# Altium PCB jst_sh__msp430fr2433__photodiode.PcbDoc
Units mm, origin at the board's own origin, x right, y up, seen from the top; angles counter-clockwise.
Board outline 56 x 30 mm, 2 copper layers (Top, Bottom), stack 0 mm thick; 17 components, 9 nets, 70 pads, 27 vias.
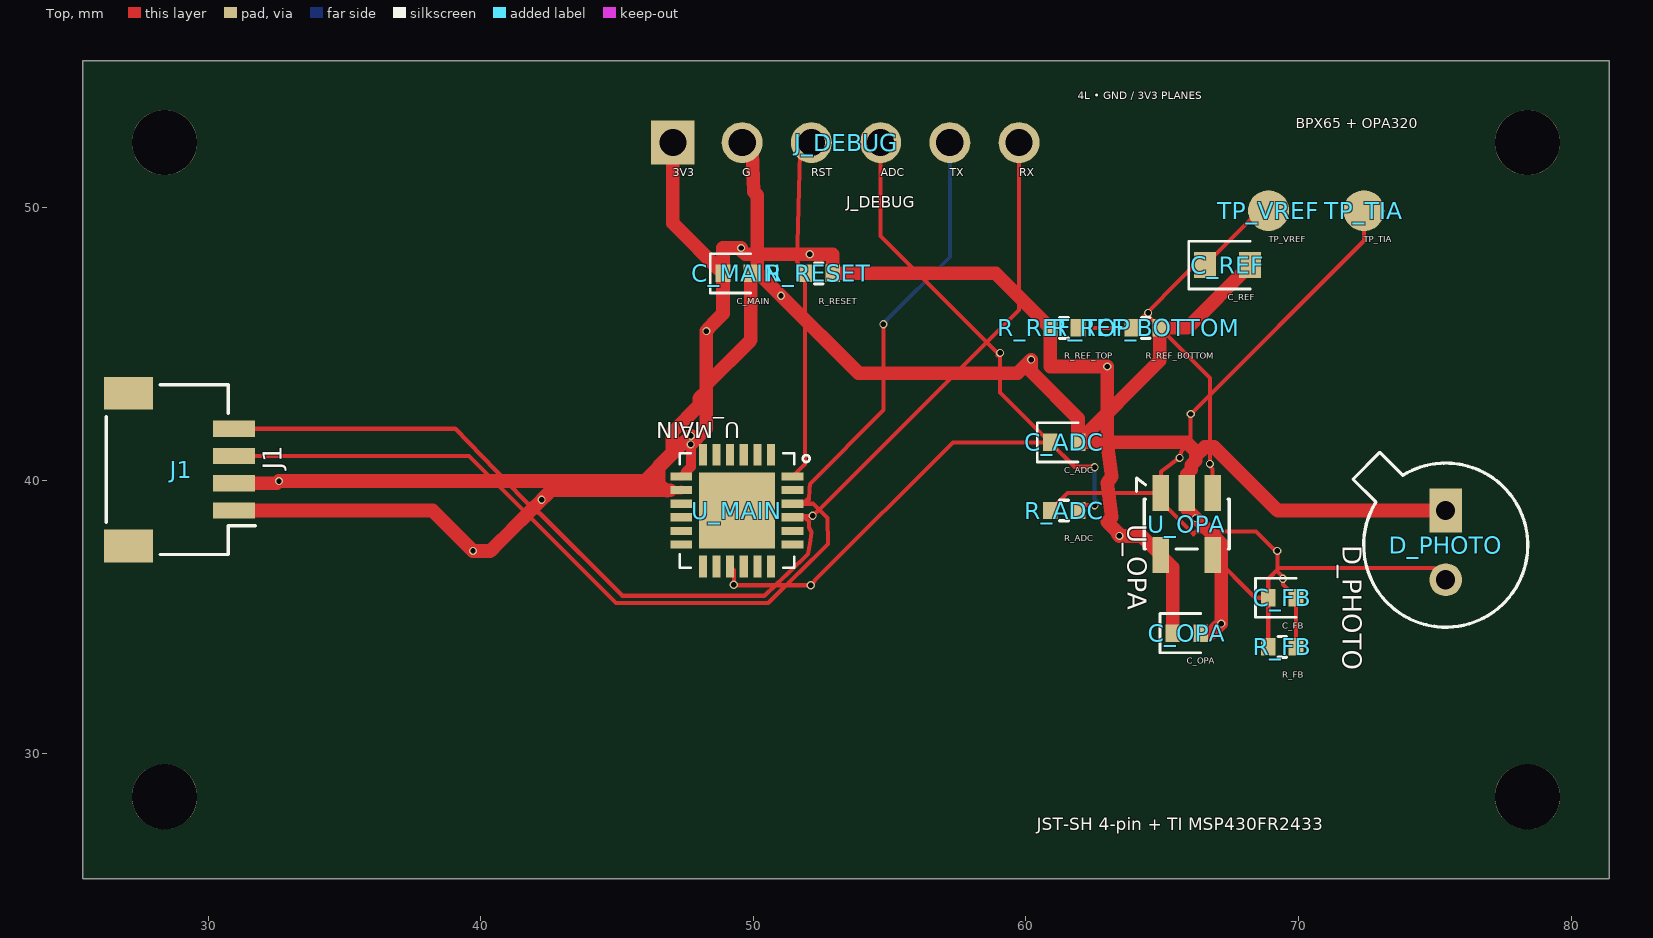
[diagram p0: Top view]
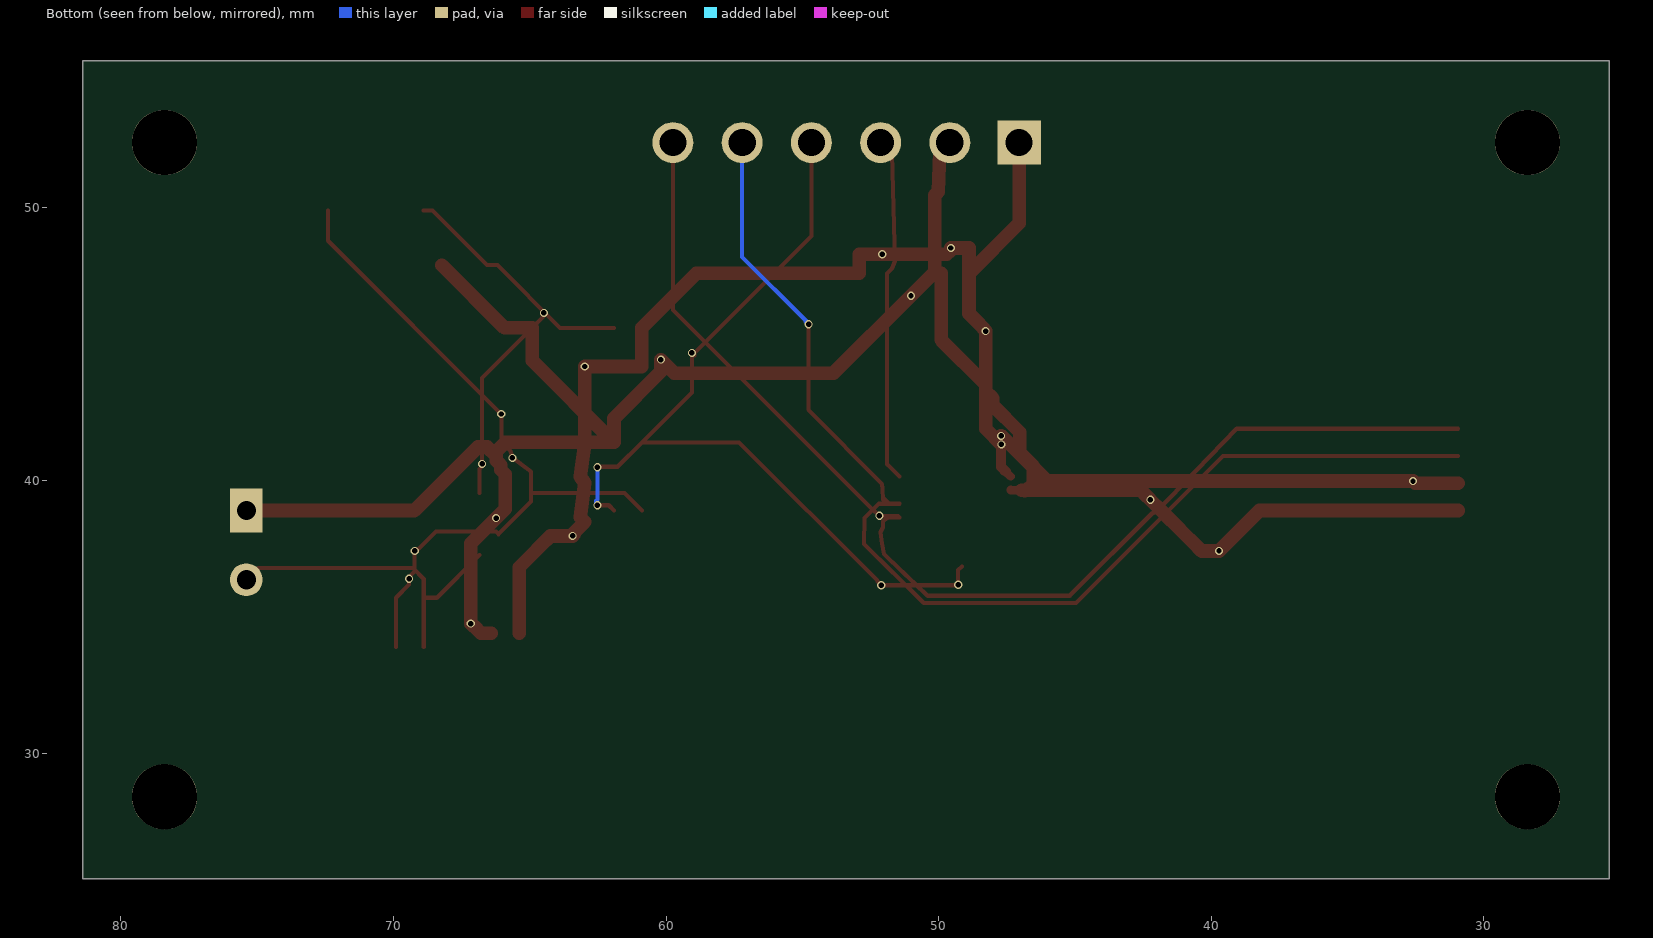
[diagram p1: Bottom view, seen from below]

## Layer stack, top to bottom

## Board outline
25.4,55.4 81.4,55.4 81.4,25.4 25.4,25.4

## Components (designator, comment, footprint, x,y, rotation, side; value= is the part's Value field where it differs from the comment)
C_ADC "" TSCIRCUIT-1.5600x0.6400mm 61.4,41.4 r0 top
C_FB "" TSCIRCUIT-1.5600x0.6400mm 69.4,35.7 r0 top
C_MAIN "" TSCIRCUIT-1.5600x0.6400mm 49.4,47.6 r0 top
C_OPA "" TSCIRCUIT-1.5600x0.6400mm 65.9,34.4 r0 top
C_REF "" TSCIRCUIT-2.4500x0.9500mm 67.4,47.9 r0 top
D_PHOTO "" TSCIRCUIT-1.2000x3.9400mm 75.4,37.73 r270 top
J1 "" TSCIRCUIT-5.5500x6.8000mm 28.95,40.4 r90 top
J_DEBUG "" TSCIRCUIT-14.2000x1.5000mm 53.4,52.4 r0 top
R_ADC "" TSCIRCUIT-1.5600x0.6400mm 61.4,38.9 r0 top
R_FB "" TSCIRCUIT-1.5600x0.6400mm 69.4,33.9 r0 top
R_REF_BOTTOM "" TSCIRCUIT-1.5600x0.6400mm 64.4,45.6 r0 top
R_REF_TOP "" TSCIRCUIT-1.5600x0.6400mm 61.4,45.6 r0 top
R_RESET "" TSCIRCUIT-1.5600x0.6400mm 52.4,47.6 r0 top
TP_TIA "" TSCIRCUIT-1.5000x1.5000mm 72.4,49.9 r0 top
TP_VREF "" TSCIRCUIT-1.5000x1.5000mm 68.9,49.9 r0 top
U_MAIN "" TSCIRCUIT-4.8833x4.8963mm 49.4,38.9 r180 top
U_OPA "" TSCIRCUIT-2.5000x3.6000mm 65.9,38.4 r270 top

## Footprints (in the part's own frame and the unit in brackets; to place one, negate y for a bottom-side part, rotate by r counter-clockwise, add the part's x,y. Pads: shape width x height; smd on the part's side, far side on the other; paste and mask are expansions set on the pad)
TSCIRCUIT-1.2000x3.9400mm [mm]
  rect 1.6x1.2 hole 0.7: 1(-1.17,0)
  round 1.2 hole 0.7: 2(1.37,0)
  silkscreen extent -3.3,-3.4 3.11,3.01
TSCIRCUIT-1.5000x1.5000mm [mm]
  round 1.5 smd: 1(0,0)
TSCIRCUIT-1.5600x0.6400mm [mm]
  rect 0.54x0.64 smd: 1(-0.51,0) 2(0.51,0)
  silkscreen extent -0.98,-0.72 0.51,0.72
TSCIRCUIT-2.4500x0.9500mm [mm]
  rect 0.8x0.95 smd: 1(-0.825,0) 2(0.825,0)
  silkscreen extent -1.43,-0.87 0.82,0.87
TSCIRCUIT-2.5000x3.6000mm [mm]
  rect 1.325x0.6 smd: 1(-1.138,-0.95) 2(-1.138,0) 3(-1.138,0.95) 4(1.137,0.95) 5(1.137,-0.95)
  silkscreen extent -1.69,-1.84 0.91,1.56
TSCIRCUIT-4.8833x4.8963mm [mm]
  rect 0.8x0.3 smd: 1(-2.042,-1.25) 2(-2.042,-0.75) 3(-2.042,-0.25) 4(-2.042,0.25) 5(-2.042,0.75) 6(-2.042,1.25) 13(2.042,1.25) 14(2.042,0.75) 15(2.042,0.25) 16(2.042,-0.25) 17(2.042,-0.75) 18(2.042,-1.25)
  rect 0.3x0.8 smd: 7(-1.25,2.048) 8(-0.75,2.048) 9(-0.25,2.048) 10(0.25,2.048) 11(0.75,2.048) 12(1.25,2.048) 19(1.25,-2.048) 20(0.75,-2.048) 21(0.25,-2.048) 22(-0.25,-2.048) 23(-0.75,-2.048) 24(-1.25,-2.048)
  rect 2.8x2.8 smd: 25(-0.001,0.001)
  silkscreen extent -2.67,-2.1 2.1,2.1
TSCIRCUIT-5.5500x6.8000mm [mm]
  rect 1.2x1.8 smd: 1(-2.8,1.875) 1(2.8,1.875)
  rect 0.6x1.55 smd: 1(-1.5,-2) 2(-0.5,-2) 3(0.5,-2) 4(1.5,-2)
  silkscreen extent -3.11,-2.77 3.11,2.69
TSCIRCUIT-14.2000x1.5000mm [mm]
  rect 1.6x1.6 hole 1: 1(-6.35,0)
  round 1.5 hole 1: 2(-3.81,0) 3(-1.27,0) 4(1.27,0) 5(3.81,0) 6(6.35,0)

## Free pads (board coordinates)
  round 2.4 hole 2.4 unplated: NPTH-1(28.4,28.4) NPTH-2(78.4,52.4) NPTH-3(78.4,28.4) NPTH-4(28.4,52.4)

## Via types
v1: diameter 0.3, hole 0.2, Top to Bottom, 27 vias

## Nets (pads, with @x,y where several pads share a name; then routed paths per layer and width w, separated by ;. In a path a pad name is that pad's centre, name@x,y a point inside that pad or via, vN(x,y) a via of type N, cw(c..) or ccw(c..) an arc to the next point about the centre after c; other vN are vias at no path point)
ADC_IN: C_ADC.1 J_DEBUG.4 R_ADC.2 U_MAIN.10 | length 32.4
  Top w0.15: U_MAIN.10 49.284,36.718 v1(49.284,36.18) 49.305,36.159 49.36,36.159 v1(52.11,36.159) 52.242,36.291 52.242,36.324 57.318,41.4 C_ADC.1 ; J_DEBUG.4 54.67,48.969 58.962,44.678 58.962,44.581 v1(59.054,44.684) 59.054,43.236 C_ADC.1 ; R_ADC.2 62.103,39.093 v1(62.522,39.093) ; v1(62.521,40.49) 62.505,40.506 61.784,40.506 C_ADC.1
  Bottom w0.15: v1(62.521,40.49) 62.521,39.299 62.561,39.258 62.561,39.132 v1(62.522,39.093)
GND: C_ADC.2 C_MAIN.2 C_OPA.2 C_REF.2 D_PHOTO.1 J1.1@30.95,38.9 J_DEBUG.2 R_REF_BOTTOM.2 U_MAIN.17 U_OPA.2 | length 82.7
  Top w0.3: U_MAIN.17@46.958,39.65 46.983,39.65 47.077,39.65 47.171,39.65 47.264,39.65 U_MAIN.17
  Top w0.324: U_MAIN.17@46.958,39.638 47.098,39.642 U_MAIN.17
  Top w0.475: 46.795,39.65 46.889,39.65 46.958,39.65 ; 46.838,39.634 U_MAIN.17@46.958,39.638
  Top w0.5: J1.1@30.95,38.9 38.233,38.9 v1(39.716,37.417) 40.036,37.417 40.356,37.417 40.663,37.724 40.971,38.032 41.278,38.339 41.585,38.646 41.893,38.954 42.2,39.261 v1(42.234,39.295) 42.412,39.472 42.589,39.65 43.036,39.65 43.482,39.65 43.929,39.65 44.375,39.65 44.822,39.65 45.268,39.65 45.715,39.65 46.161,39.65 46.608,39.65 46.702,39.65 46.795,39.65 ; 46.838,39.634 46.6,39.8 46.525,39.875 46.525,40.525 47.025,41.025 47.025,41.775 48.025,42.775 48.025,43.025 48.275,43.275 48.275,43.525 49.91,45.16 49.91,45.308 49.91,45.766 49.91,46.225 49.91,46.683 49.91,47.142 C_MAIN.2 ; J_DEBUG.2 49.774,52.223 49.951,52.047 49.958,52.047 49.979,51.561 50,51.076 50.021,50.59 50.15,50.461 50.15,48.65 50.146,47.677 C_MAIN.2 ; C_OPA.2 66.788,34.4 67.051,34.663 67.078,34.663 v1(67.165,34.75) 67.165,37.69 v1(66.234,38.621) 65.9,38.955 U_OPA.2 ; C_REF.2 65.925,45.6 R_REF_BOTTOM.2 64.91,44.4 C_ADC.2 ; D_PHOTO.1 69.233,38.9 66.9,41.233 66.567,41.233 66.233,40.9 66.233,40.733 ; C_MAIN.2 50.197,47.6 v1(51.016,46.781) 53.856,43.941 59.64,43.941 59.697,43.941 v1(60.192,44.436) 60.192,43.997 61.91,42.279 C_ADC.2 ; C_ADC.2 62.067,41.4 65.9,41.4 66.233,41.067 66.233,40.733 ; U_OPA.2 65.9,40.233 ; U_OPA.2 65.9,40.233 ; 65.9,40.233 66.067,40.4 ; 65.9,40.233 66.067,40.4 ; 66.067,40.4 66.067,40.567 ; 66.067,40.4 66.067,40.567 ; 66.067,40.567 66.233,40.733 ; 66.067,40.567 66.233,40.733
MAIN_RESET: J_DEBUG.3 R_RESET.1 U_MAIN.1 | length 12.7
  Top w0.15: U_MAIN.1 51.89,40.598 R_RESET.1 51.713,47.777 51.6,48.05 51.713,51.983 J_DEBUG.3
PD_SUM: C_FB.1 D_PHOTO.2 R_FB.1 U_OPA.4 | length 12
  Top w0.15: U_OPA.4 68.412,35.7 C_FB.1 ; R_FB.1 C_FB.1 ; D_PHOTO.2 74.976,36.784 69.29,36.784 68.89,36.384 C_FB.1
TIA_OUT: C_FB.2 R_ADC.1 R_FB.2 TP_TIA.1 U_OPA.1 | length 27
  Top w0.15: R_ADC.1 61.527,39.538 U_OPA.1 ; R_FB.2 C_FB.2 69.426,36.184 v1(69.426,36.395) 69.392,36.429 69.392,36.492 69.223,36.661 v1(69.223,37.42) 69.161,37.482 69.085,37.482 68.439,38.128 68.353,38.128 66.245,38.128 66.148,38.031 64.949,39.237 U_OPA.1 ; TP_TIA.1 72.4,48.797 66.123,42.52 v1(66.044,42.441) 66.044,41.42 65.706,41.082 65.706,41.078 v1(65.636,40.832) 64.95,40.322 U_OPA.1
UART_MAIN_RX: J1.4 J_DEBUG.6 U_MAIN.4 | length 43.7
  Top w0.15: J1.4 39.066,41.9 42.038,38.825 42.166,38.8 45.191,35.775 49.911,35.775 50.402,35.775 51.89,37.2 52.011,37.311 52.072,37.691 52.131,38.089 52.047,38.3 52.048,38.5 51.842,38.65 51.838,38.65 51.771,38.65 51.749,38.65 51.734,38.65 51.72,38.65 51.703,38.65 51.683,38.65 51.66,38.65 51.635,38.65 51.611,38.65 51.587,38.65 51.562,38.65 51.537,38.65 51.512,38.65 51.487,38.65 51.463,38.65 U_MAIN.4 51.498,38.706 v1(52.174,38.706) 52.331,38.863 52.352,38.863 59.75,46.261 J_DEBUG.6
UART_MAIN_TX: J1.3 J_DEBUG.5 U_MAIN.3 | length 43.3
  Top w0.15: J1.3 39.576,40.9 44.967,35.509 50.548,35.501 52.737,37.665 52.716,38.625 52.191,39.15 U_MAIN.3 ; U_MAIN.3 51.817,39.148 52.041,39.373 52.038,39.298 52.055,39.697 52.083,39.864 54.774,42.595 v1(54.774,45.734)
  Bottom w0.15: v1(54.774,45.734) 54.877,45.837 54.877,45.867 57.21,48.2 J_DEBUG.5
VCC_3V3: C_MAIN.1 C_OPA.1 J1.2 J_DEBUG.1 R_REF_TOP.1 R_RESET.2 U_MAIN.18 U_OPA.5 | length 62.3
  Top w0.3: U_MAIN.18 47.508,40.3 U_MAIN.18
  Top w0.325: 47.712,40.504 47.535,40.327 ; 47.535,40.327 47.508,40.3 47.535,40.327
  Top w0.35: v1(47.7,41.325) v1@47.712,41.261 ; 47.712,40.882 v1@47.712,41.261 ; v1(47.712,41.639) v1@47.712,41.261
  Top w0.375: 47.535,40.327 47.712,40.504 ; v1@47.712,41.261 47.712,40.882 ; 47.712,40.504 47.712,40.882 ; 47.712,40.504 47.712,40.882
  Top w0.5: J1.2 32.518,39.9 v1(32.599,39.981) 33.096,39.981 33.594,39.981 34.091,39.981 34.589,39.981 35.086,39.981 35.584,39.981 36.081,39.981 36.579,39.981 37.076,39.981 37.574,39.981 38.071,39.981 38.569,39.981 39.066,39.981 39.564,39.981 40.061,39.981 40.559,39.981 41.056,39.981 41.554,39.981 42.051,39.981 42.549,39.981 43.046,39.981 43.544,39.981 44.041,39.981 44.539,39.981 45.036,39.981 45.534,39.981 46.031,39.981 46.359,40.309 46.687,40.636 47.014,40.964 47.342,41.291 47.669,41.619 47.692,41.619 v1(47.712,41.639) ; J_DEBUG.1 47.05,49.44 C_MAIN.1 ; v1(47.7,41.325) 48.277,41.902 v1(48.277,45.484) 48.343,45.55 48.343,45.577 48.617,45.85 48.89,46.123 48.89,46.615 48.89,47.108 C_MAIN.1 ; C_OPA.1 65.39,36.822 U_OPA.5 64.598,37.615 64.245,37.967 63.837,37.967 v1(63.43,37.967) 63.372,38.025 63.372,38.095 63.178,38.289 62.985,38.482 63.15,38.65 62.985,39.908 63.15,40.15 62.985,41.333 62.985,41.808 62.985,42.283 62.985,42.759 62.985,43.234 62.985,43.709 v1(62.985,44.184) 60.89,44.184 R_REF_TOP.1 58.89,47.6 R_RESET.2 52.91,48.301 v1(52.069,48.301) 51.597,48.301 51.125,48.301 50.653,48.301 50.181,48.301 49.708,48.301 49.611,48.398 49.602,48.398 v1(49.549,48.531) 48.89,48.531 C_MAIN.1
VREF_0V5: C_REF.1 R_REF_BOTTOM.1 R_REF_TOP.2 TP_VREF.1 U_OPA.3 | length 17.2
  Top w0.15: R_REF_TOP.2 R_REF_BOTTOM.1 ; U_OPA.3 66.85,40.418 66.766,40.502 66.766,40.593 v1(66.751,40.608) 66.751,43.765 64.524,45.992 64.524,46.108 v1(64.481,46.151) 64.441,46.151 R_REF_BOTTOM.1 ; TP_VREF.1 68.575,49.9 C_REF.1 66.19,47.9 R_REF_BOTTOM.1
pads on no net: J1.1@27.075,37.6 J1.1@27.075,43.2 U_MAIN.2 U_MAIN.5 U_MAIN.6 U_MAIN.7 U_MAIN.8 U_MAIN.9 U_MAIN.11 U_MAIN.12 U_MAIN.13 U_MAIN.14 U_MAIN.15 U_MAIN.16 U_MAIN.19 U_MAIN.20 U_MAIN.21 U_MAIN.22 U_MAIN.23 U_MAIN.24 U_MAIN.25

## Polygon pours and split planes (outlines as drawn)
GND on Mid1 (solid): 81.1,55.1 25.7,55.1 25.7,25.7 81.1,25.7
VCC_3V3 on Mid2 (solid): 81.1,55.1 25.7,55.1 25.7,25.7 81.1,25.7

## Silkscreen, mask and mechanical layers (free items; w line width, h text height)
Top Overlay:
  text "4L • GND / 3V3 PLANES" at 61.9,53.9 h0.48
  text "BPX65 + OPA320" at 69.9,52.8 h0.65
  text "JST-SH 4-pin + TI MSP430FR2433" at 60.4,27 h0.78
